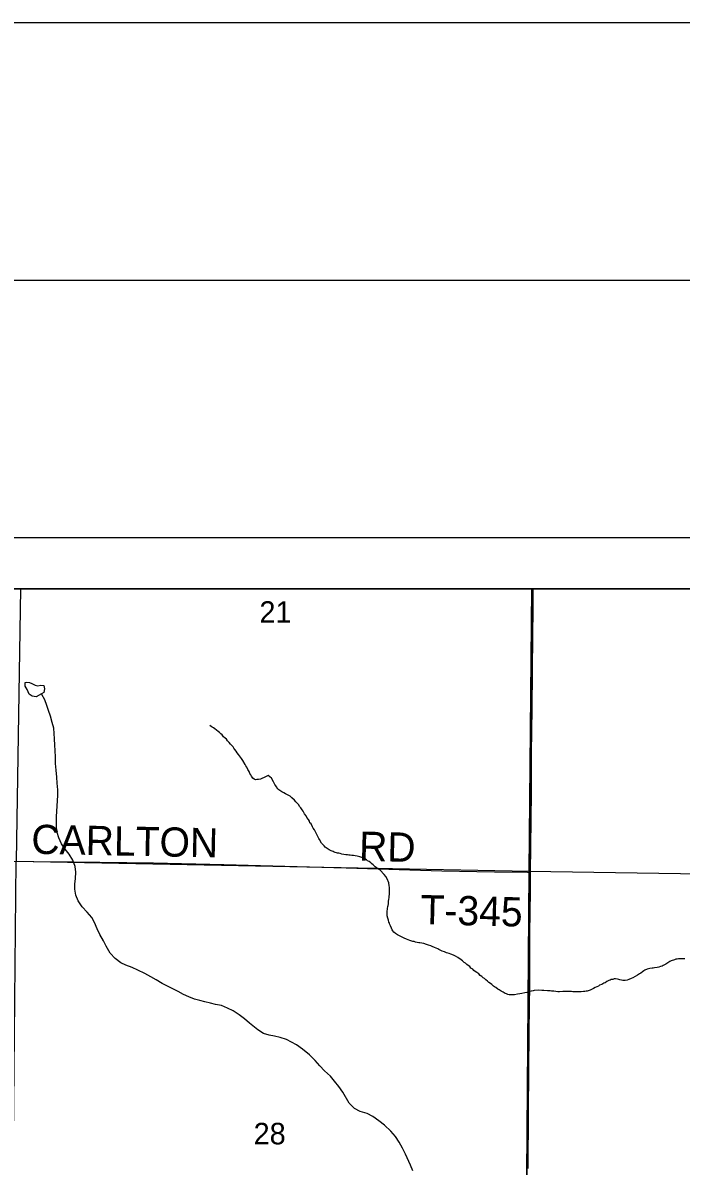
# Model space of a CAD drawing. Extents: x 0 to 34, y 0 to 22.
# Drawn here: x 5.509 to 6.788, y 19.778 to 22 of the extents above; entities that cross this region are included whole.
import ezdxf

# ---------------------------------------------------------------- set-up
doc = ezdxf.new("R2010")
doc.units = 0
for name, color, linetype in [('GM_X_Corporation', 7, 'Continuous'), ('GM_X_Minor_River', 7, 'Continuous'), ('GM_X_Section_Text', 7, 'Continuous'), ('GM_X_State_Route', 7, 'Continuous'), ('GM_X_Township_Road', 7, 'Continuous'), ('GM_X_Township_Road_Text', 7, 'Continuous'), ('SH_Border', 7, 'Continuous'), ('SH_Cut_Line', 7, 'Continuous'), ('SH_Data', 7, 'Continuous')]:
    doc.layers.add(name, color=color, linetype=linetype)

msp = doc.modelspace()

# ---------------------------------------------------------------- linework, layer by layer
at = {"layer": 'GM_X_Corporation'}
msp.add_lwpolyline([(8.9, 20.9), (3.5231, 20.9), (3.5228, 20.8664), (3.5224, 20.8347), (3.5214, 20.7384), (3.5203, 20.6635), (3.5197, 20.5949), (3.5191, 20.549), (3.5181, 20.4924), (3.5169, 20.4148), (3.5163, 20.3526), (3.5155, 20.3135), (3.5145, 20.2333), (3.5137, 20.1344), (3.5125, 20.0737), (3.5112, 20.0053), (3.511, 19.9493), (3.5095, 19.8637), (3.5082, 19.7748)], dxfattribs=at)
for points in [[(6.4979, 20.9), (5.5043, 20.9), (5.4958, 20.3705), (6.4927, 20.3511)], [(7.5063, 20.9), (6.4979, 20.9), (6.4927, 20.3511), (7.5004, 20.336)], [(5.4958, 20.3705), (6.4927, 20.3511), (6.4855, 19.3379), (5.4859, 19.36)], [(6.4927, 20.3511), (7.5004, 20.336), (7.4935, 19.3206), (6.4855, 19.3379)]]:
    msp.add_lwpolyline(points, close=True, dxfattribs=at)
at = {"layer": 'GM_X_Minor_River'}
for points in [[(5.5447, 20.696), (5.5344, 20.6904), (5.5271, 20.6914), (5.521, 20.6955), (5.5171, 20.7045), (5.5134, 20.7106), (5.5132, 20.7182), (5.5166, 20.7189), (5.5215, 20.7181), (5.5264, 20.7161), (5.5325, 20.7129), (5.5381, 20.7113), (5.5438, 20.7131), (5.5495, 20.7122), (5.5509, 20.7057)], [(5.5509, 20.7057), (5.5494, 20.6983), (5.5447, 20.696)], [(5.6784, 20.192), (5.6707, 20.2054), (5.6652, 20.2161), (5.6586, 20.228), (5.6531, 20.2391), (5.648, 20.2514), (5.6429, 20.261), (5.634, 20.2714), (5.6243, 20.2818), (5.6162, 20.2937), (5.6118, 20.3045), (5.6101, 20.3163), (5.6099, 20.3261), (5.6113, 20.3371), (5.6115, 20.3496), (5.6102, 20.3607), (5.6062, 20.3725), (5.5989, 20.3844), (5.5911, 20.3944), (5.5837, 20.4048), (5.579, 20.4163), (5.5757, 20.4266), (5.574, 20.4361), (5.5744, 20.4578), (5.5755, 20.4779), (5.5761, 20.4885), (5.5767, 20.4984), (5.5769, 20.5094), (5.5756, 20.5223), (5.5747, 20.5341), (5.5738, 20.5478), (5.5721, 20.5603), (5.572, 20.5729), (5.5718, 20.5861), (5.5709, 20.5964), (5.57, 20.6086), (5.5698, 20.6192), (5.5689, 20.6295), (5.566, 20.6402), (5.5628, 20.6524), (5.5589, 20.6638), (5.5556, 20.6734), (5.5517, 20.6841), (5.5458, 20.6948), (5.5447, 20.696)], [(5.9637, 20.5294), (5.961, 20.529), (5.9583, 20.5299), (5.9557, 20.5322), (5.9531, 20.5357), (5.9516, 20.5384), (5.9498, 20.5411), (5.9484, 20.5453), (5.9462, 20.5492), (5.944, 20.5534), (5.9421, 20.5561), (5.9406, 20.5588), (5.9362, 20.5665), (5.9336, 20.57), (5.9318, 20.5727), (5.9296, 20.5754), (5.9277, 20.5781), (5.9255, 20.5812), (5.9233, 20.5847), (5.9207, 20.5878), (5.9188, 20.5905), (5.9173, 20.5928), (5.9121, 20.5983), (5.9095, 20.6014), (5.9065, 20.6049), (5.9043, 20.6076), (5.9017, 20.6099), (5.899, 20.6126), (5.8961, 20.6161), (5.8934, 20.6181), (5.8908, 20.6208), (5.8882, 20.6228), (5.8852, 20.6255), (5.8822, 20.6279), (5.8791, 20.6299), (5.8769, 20.6314), (5.8746, 20.6326), (5.8723, 20.6342)], [(6.2178, 20.2769), (6.2179, 20.2791), (6.2184, 20.2825), (6.2188, 20.2848), (6.2193, 20.2878), (6.2197, 20.2905), (6.2198, 20.2932), (6.2203, 20.2962), (6.2208, 20.3003), (6.2208, 20.303), (6.2213, 20.3057), (6.2215, 20.3121), (6.2215, 20.3148), (6.2213, 20.3201), (6.221, 20.3231), (6.2204, 20.3285), (6.2167, 20.3362), (6.2142, 20.3408), (6.2112, 20.345), (6.2034, 20.3532), (6.2011, 20.3544), (6.1988, 20.3564), (6.1962, 20.358), (6.1935, 20.3599), (6.1898, 20.3634), (6.1872, 20.3658), (6.1849, 20.3677), (6.1819, 20.3701), (6.1789, 20.3717), (6.1766, 20.3733), (6.1736, 20.3752), (6.1705, 20.3764), (6.1675, 20.378), (6.1641, 20.3793), (6.161, 20.3797), (6.1587, 20.3802), (6.1545, 20.3814), (6.1515, 20.3819), (6.1484, 20.3819), (6.1453, 20.3824), (6.1427, 20.3825), (6.1396, 20.3829), (6.1365, 20.383), (6.1289, 20.3847), (6.1254, 20.3855), (6.1228, 20.3864), (6.1201, 20.3864), (6.114, 20.3881), (6.1117, 20.3893), (6.1079, 20.3909), (6.1045, 20.3929), (6.1022, 20.3941), (6.0985, 20.3968), (6.0962, 20.398), (6.0947, 20.4004), (6.0895, 20.4058), (6.0851, 20.4128), (6.084, 20.4151), (6.0825, 20.4174), (6.0814, 20.4201), (6.0799, 20.4228), (6.0789, 20.4251), (6.076, 20.4316), (6.0734, 20.4347), (6.0719, 20.4374), (6.069, 20.4432), (6.0667, 20.4455), (6.0657, 20.4486), (6.0638, 20.4517), (6.0608, 20.4555), (6.0594, 20.459), (6.0564, 20.4629), (6.0539, 20.4679), (6.0516, 20.4706), (6.0494, 20.4744), (6.0468, 20.4768), (6.045, 20.4802), (6.042, 20.4837), (6.0394, 20.4861), (6.0371, 20.4892), (6.0319, 20.4939), (6.0281, 20.497), (6.0255, 20.4986), (6.0194, 20.5018), (6.016, 20.5034), (6.0122, 20.5054), (6.01, 20.5069), (6.0047, 20.5109), (6.0021, 20.5151), (6.0002, 20.5174), (5.9988, 20.5198), (5.9962, 20.5251), (5.9918, 20.5321), (5.9888, 20.5344), (5.9858, 20.5372), (5.9803, 20.5346), (5.9768, 20.5328), (5.9745, 20.5318), (5.9706, 20.5303), (5.9668, 20.5297), (5.9637, 20.5294)], [(6.5364, 20.1181), (6.5337, 20.1186), (6.5314, 20.1186), (6.5283, 20.1191), (6.5218, 20.1193), (6.5176, 20.1197), (6.5107, 20.1199), (6.503, 20.1193), (6.5006, 20.1186), (6.4968, 20.118), (6.4925, 20.1169), (6.4886, 20.1155), (6.4848, 20.1149), (6.4786, 20.1135), (6.4751, 20.1128), (6.4701, 20.1122), (6.4647, 20.1112), (6.462, 20.1109), (6.4543, 20.111), (6.4517, 20.1115), (6.4486, 20.1127), (6.446, 20.1139), (6.4426, 20.1159), (6.4384, 20.1183), (6.4346, 20.121), (6.432, 20.1222), (6.4282, 20.125), (6.4259, 20.1266), (6.4237, 20.1278), (6.4203, 20.1309), (6.418, 20.1328), (6.4146, 20.1348), (6.412, 20.1375), (6.4086, 20.1399), (6.406, 20.1426), (6.4033, 20.1438), (6.4011, 20.1469), (6.3977, 20.1485), (6.3951, 20.1516), (6.3913, 20.1544), (6.3879, 20.1564), (6.3857, 20.158), (6.3834, 20.1611), (6.3793, 20.1631), (6.3774, 20.1658), (6.3744, 20.1677), (6.3721, 20.1701), (6.3695, 20.1724), (6.3669, 20.174), (6.3631, 20.1771), (6.3609, 20.1791), (6.3541, 20.1838), (6.3499, 20.1862), (6.3457, 20.1882), (6.3408, 20.1902), (6.3377, 20.1914), (6.3347, 20.1919), (6.3324, 20.1927), (6.3282, 20.1943), (6.324, 20.1956), (6.3214, 20.1972), (6.3176, 20.1988), (6.3153, 20.2004), (6.3119, 20.202), (6.3092, 20.2028), (6.3043, 20.2052), (6.3016, 20.206), (6.2974, 20.2073), (6.2933, 20.2089), (6.2879, 20.2105), (6.2845, 20.2114), (6.2807, 20.2118), (6.2784, 20.2123), (6.2753, 20.2127), (6.2719, 20.2136), (6.2692, 20.2144), (6.2669, 20.2148), (6.2631, 20.2161), (6.2608, 20.2169), (6.2578, 20.2177), (6.2543, 20.2193), (6.2498, 20.2214), (6.2464, 20.2233), (6.2407, 20.2254), (6.2369, 20.2274), (6.2331, 20.2301), (6.2297, 20.2329), (6.2279, 20.2352), (6.2264, 20.2375), (6.2253, 20.2406), (6.2231, 20.2448), (6.2221, 20.2475), (6.2214, 20.2502), (6.2203, 20.2525), (6.2196, 20.2559), (6.2185, 20.2597), (6.2171, 20.2643), (6.2168, 20.2681), (6.2169, 20.2719), (6.217, 20.2742), (6.2178, 20.2769)], [(6.2667, 19.7687), (6.262, 19.7798), (6.2525, 19.8013), (6.2466, 19.8131), (6.24, 19.8247), (6.233, 19.8358), (6.2241, 19.8462), (6.2118, 19.8574), (6.2009, 19.8664), (6.189, 19.8746), (6.1781, 19.8801), (6.1645, 19.8845), (6.1532, 19.8904), (6.1428, 19.9005), (6.1306, 19.9216), (6.1229, 19.9331), (6.1147, 19.9435), (6.1066, 19.9532), (6.0954, 19.9633), (6.0861, 19.9733), (6.0768, 19.9837), (6.066, 19.9946), (6.0525, 20.0051), (6.0409, 20.0136), (6.0311, 20.0191), (6.0213, 20.0239), (6.0089, 20.0283), (5.9976, 20.0304), (5.9877, 20.0325), (5.9768, 20.0361), (5.9652, 20.0428), (5.9495, 20.056), (5.9398, 20.0645), (5.9293, 20.0723), (5.9173, 20.0797), (5.9064, 20.0852), (5.8951, 20.09), (5.8834, 20.0925), (5.8735, 20.095), (5.8626, 20.0974), (5.8528, 20.0999), (5.8422, 20.1027), (5.8313, 20.1071), (5.8211, 20.1115), (5.8106, 20.1178), (5.791, 20.1272), (5.7794, 20.1332), (5.7678, 20.1402), (5.7576, 20.1457), (5.746, 20.1524), (5.7324, 20.1591), (5.7212, 20.1642), (5.7091, 20.1686), (5.6989, 20.173), (5.6885, 20.1815), (5.6784, 20.192)], [(6.7958, 20.1809), (6.7866, 20.1812), (6.7832, 20.1809), (6.7805, 20.1805), (6.7781, 20.1802), (6.7758, 20.1791), (6.7688, 20.177), (6.7665, 20.1759), (6.7587, 20.1708), (6.7563, 20.1694), (6.7536, 20.1679), (6.7513, 20.1668), (6.7482, 20.1658), (6.7451, 20.1651), (6.742, 20.164), (6.7366, 20.1634), (6.7343, 20.1631), (6.732, 20.1631), (6.7273, 20.1625), (6.725, 20.1618), (6.7223, 20.1611), (6.718, 20.1589), (6.7157, 20.1574), (6.7133, 20.1556), (6.7098, 20.153), (6.7075, 20.1519), (6.7036, 20.1494), (6.6989, 20.1468), (6.6942, 20.1439), (6.6915, 20.1428), (6.6868, 20.1407), (6.6833, 20.1396), (6.6798, 20.1389), (6.6748, 20.1391), (6.6726, 20.1395), (6.6695, 20.1403), (6.6672, 20.1411), (6.6649, 20.1416), (6.6607, 20.1421), (6.6584, 20.1421), (6.6553, 20.1411), (6.6526, 20.1407), (6.6503, 20.1393), (6.6476, 20.1386), (6.6441, 20.1368), (6.6405, 20.1342), (6.6382, 20.1335), (6.6343, 20.1313), (6.63, 20.1295), (6.6277, 20.1277), (6.6242, 20.1266), (6.6215, 20.1252), (6.6183, 20.1233), (6.6113, 20.1201), (6.6059, 20.1183), (6.6036, 20.118), (6.6013, 20.1173), (6.5986, 20.1174), (6.5943, 20.1171), (6.592, 20.1168), (6.5867, 20.1169), (6.584, 20.1166), (6.5801, 20.1171), (6.5778, 20.1171), (6.5751, 20.1176), (6.5725, 20.1176), (6.5701, 20.1173), (6.5625, 20.1175), (6.5586, 20.1172), (6.5517, 20.1166), (6.5486, 20.1167), (6.5448, 20.1176), (6.541, 20.118), (6.5364, 20.1181)]]:
    msp.add_lwpolyline(points, dxfattribs=at)
at = {"layer": 'GM_X_State_Route'}
msp.add_lwpolyline([(6.4907, 19.7736), (6.4915, 19.8842), (6.4931, 20.0401), (6.494, 20.1327), (6.4945, 20.2308), (6.4953, 20.3122), (6.4956, 20.349), (6.496, 20.3992), (6.4975, 20.5042), (6.4977, 20.5806), (6.4987, 20.6676), (6.4998, 20.8097), (6.5006, 20.8592), (6.5007, 20.9)], dxfattribs=at)
at = {"layer": 'GM_X_Township_Road'}
msp.add_lwpolyline([(5.3773, 20.3715), (5.6065, 20.3695), (5.763, 20.3674), (5.8996, 20.3644), (6.1375, 20.3578), (6.3231, 20.3521), (6.4256, 20.35), (6.4895, 20.3491), (6.4956, 20.349)], dxfattribs=at)
at = {"layer": 'SH_Border'}
msp.add_lwpolyline([(1.5, 21.5), (33.5, 21.5), (33.5, 0.5), (1.5, 0.5)], close=True, dxfattribs=at)
at = {"layer": 'SH_Cut_Line'}
msp.add_lwpolyline([(0, 0), (34, 0), (34, 22), (0, 22)], close=True, dxfattribs=at)
at = {"layer": 'SH_Data'}
for p, q in [((2, 21), (9, 21)), ((2.1, 20.9), (8.9, 20.9)), ((2.1, 20.9), (8.9, 20.9)), ((2.1, 20.9), (8.9, 20.9))]:
    msp.add_line(p, q, dxfattribs=at)

# ---------------------------------------------------------------- texts
at = {"layer": 'GM_X_Section_Text'}
for s, p in [('21', (5.9687, 20.8341)), ('28', (5.9574, 19.8204))]:
    msp.add_text(s, height=0.04186, rotation=0, dxfattribs=at).set_placement(p)
at = {"layer": 'GM_X_Township_Road_Text'}
for s, rotation, p in [('CARLTON', 358.8363, (5.5249, 20.3852)), ('RD', 358.5194, (6.1617, 20.3718)), ('T-345', 358.5957, (6.2812, 20.2484))]:
    msp.add_text(s, height=0.05682, rotation=rotation, dxfattribs=at).set_placement(p)

doc.saveas('drawing.dxf')
